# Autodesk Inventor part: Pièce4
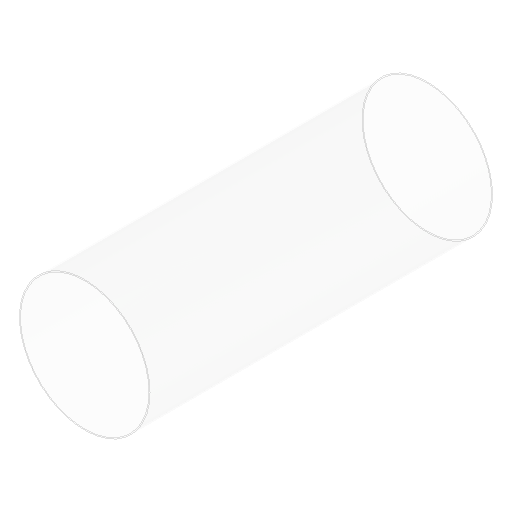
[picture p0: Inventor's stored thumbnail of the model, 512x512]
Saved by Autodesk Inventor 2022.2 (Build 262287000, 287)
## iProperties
Created: 2016-10
Part Number: Pièce4
Material: solidworks materials|Verre
Document SubType Name: Modeling
Designer: 18907419
Density: 2.4576 g/cm^3
Appearance: Default
Author: 18907419
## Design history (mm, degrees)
feature "Solido1"
node "Solido2"
